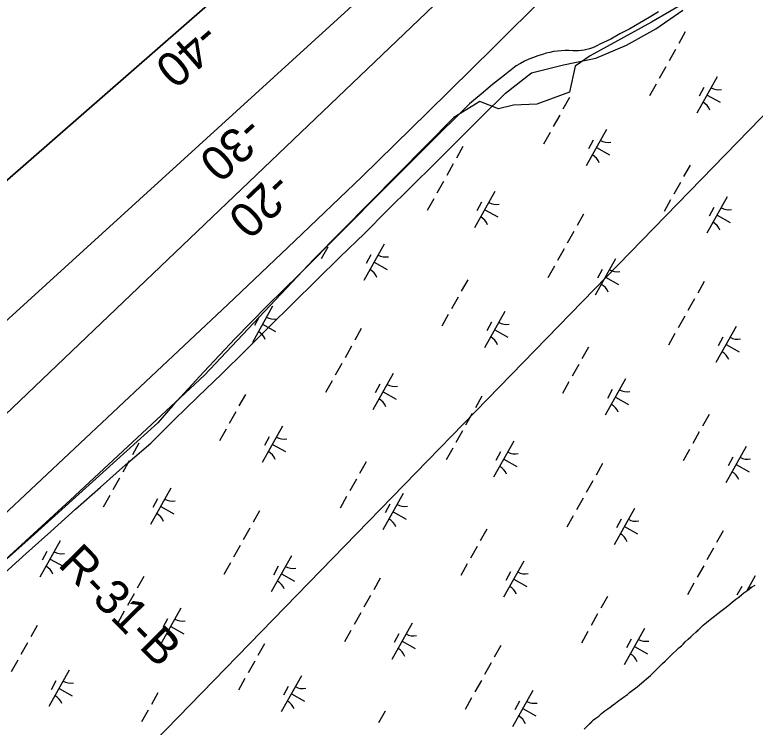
# Model space of a CAD drawing. Extents: x 3923531 to 3943530, y 207391 to 229799.
# Drawn here: x 3930996 to 3931887, y 212001 to 212858 of the extents above; entities that cross this region are included whole.
import ezdxf

# ---------------------------------------------------------------- set-up
doc = ezdxf.new("R2010")
doc.units = 0
for name, color, linetype in [('V-RIVR-EDGE', 7, 'Continuous'), ('V-RIVR-RANG-IDEN', 7, 'Continuous'), ('V-RRAP-FSHR', 7, 'Continuous'), ('V-TOPO-DPTH', 7, 'Continuous'), ('V-TOPO-MINR', 7, 'Continuous'), ('V-TOPO-MINR-IDEN', 7, 'Continuous'), ('V-TOPO-SHOR', 7, 'Continuous'), ('V-UTIL-LINE', 7, 'Continuous'), ('V-WETL-SWMP', 7, 'Continuous')]:
    doc.layers.add(name, color=color, linetype=linetype)

msp = doc.modelspace()

# ---------------------------------------------------------------- linework, layer by layer
at = {"layer": 'V-RIVR-EDGE'}
msp.add_lwpolyline([(3931806.48, 212875.19), (3931762.67, 212849.35), (3931688.52, 212808.91), (3931670.55, 212796.55), (3931663.81, 212765.1), (3931624.49, 212750.49), (3931596.4, 212749.37), (3931578.43, 212744.87), (3931555.96, 212753.86), (3931524.5, 212734.76), (3931355.99, 212564.01), (3931224.55, 212424.7), (3931062.78, 212274.17), (3930877.42, 212104.53)], dxfattribs=at)
at = {"layer": 'V-RRAP-FSHR'}
msp.add_lwpolyline([(3930979.93, 212183.18), (3931009.66, 212209.93), (3931039.5, 212236.57), (3931069.34, 212263.2), (3931099.35, 212289.65), (3931129.39, 212316.58), (3931159.75, 212342.87), (3931187.83, 212370.67), (3931216.59, 212398.47), (3931245.34, 212426.28), (3931273.78, 212454.4), (3931302.22, 212482.54), (3931330.65, 212510.67), (3931359.13, 212538.76), (3931387.61, 212566.84), (3931416.93, 212594.93), (3931444.57, 212623.19), (3931473.37, 212651.12), (3931501.51, 212679.21), (3931529.92, 212707.37), (3931558.2, 212735.65), (3931586.69, 212763.72), (3931618.12, 212788.32), (3931656.45, 212798.12), (3931695.57, 212806.14), (3931732.38, 212821.6), (3931767.67, 212841.5), (3931800.17, 212863.94)], dxfattribs=at)
at = {"layer": 'V-TOPO-DPTH'}
for points in [[(3930696.56, 212226.99), (3931622.64, 213069.98), (3931625.87, 213070.96), (3931629.26, 213071.55), (3931632.61, 213072.19), (3931635.76, 213073.25), (3931638.63, 213074.94), (3931641.3, 213077.06), (3931849.31, 213281.77), (3931932.2, 213361.55), (3932016.22, 213440.09), (3932101.96, 213516.75), (3932188.84, 213592.17), (3932358.19, 213735.93), (3932361.4, 213738.15), (3932364.79, 213739.91), (3932368.46, 213740.98), (3932372.32, 213741.58), (3932376.12, 213742.25), (3932379.68, 213743.44), (3932382.88, 213745.39), (3932385.85, 213747.87), (3932595.3, 213968.31)], [(3932595.3, 213968.31), (3932385.85, 213747.87), (3932382.88, 213745.39), (3932379.68, 213743.44), (3932376.12, 213742.25), (3932372.32, 213741.58), (3932368.46, 213740.98), (3932364.79, 213739.91), (3932361.4, 213738.15), (3932358.19, 213735.93), (3932188.84, 213592.17), (3932101.96, 213516.75), (3932016.22, 213440.09), (3931932.2, 213361.55), (3931849.31, 213281.77), (3931641.3, 213077.06), (3931638.63, 213074.94), (3931635.76, 213073.25), (3931632.61, 213072.19), (3931629.26, 213071.55), (3931625.87, 213070.96), (3931622.64, 213069.98), (3930696.56, 212226.99)], [(3930768.14, 212468.73), (3931535.57, 213138.53), (3931538.74, 213139.85), (3931542.06, 213140.71), (3931545.49, 213141.27), (3931548.86, 213141.9), (3931552.06, 213142.93), (3931554.99, 213144.56), (3931557.76, 213146.59), (3931734.7, 213304.83), (3931825.07, 213387.07), (3931914.46, 213470.33), (3932002.4, 213555.13), (3932089.36, 213640.96), (3932264.28, 213816.62)], [(3932264.28, 213816.62), (3932089.36, 213640.96), (3932002.4, 213555.13), (3931914.46, 213470.33), (3931825.07, 213387.07), (3931734.7, 213304.83), (3931557.76, 213146.59), (3931554.99, 213144.56), (3931552.06, 213142.93), (3931548.86, 213141.9), (3931545.49, 213141.27), (3931542.06, 213140.71), (3931538.74, 213139.85), (3931535.57, 213138.53), (3930768.14, 212468.73)], [(3932528.01, 213801.19), (3932507.12, 213780.69), (3932486.21, 213760.19), (3932465.3, 213739.7), (3932424.5, 213699.74), (3932422.94, 213698.24), (3932420.81, 213696.3), (3932420.27, 213695.83), (3931845.18, 213189.82), (3931816.27, 213164.23), (3931787.46, 213138.51), (3931758.82, 213112.62), (3931730.28, 213086.62), (3931674.64, 213035.61), (3931674, 213035.02), (3931673.36, 213034.42), (3931670.81, 213032.03), (3931669.54, 213030.84), (3930352.57, 211774.01)]]:
    msp.add_lwpolyline(points, dxfattribs=at)
at = {"layer": 'V-TOPO-MINR'}
for points in [[(3930836.96, 212119.61), (3931252.52, 212509.78), (3931333.35, 212586.34), (3931413.71, 212663.37), (3931493.4, 212741.11), (3931572.62, 212819.32), (3931696.28, 212942.47), (3931713.45, 212959.34), (3931730.77, 212976.05), (3931748.32, 212992.51), (3931766.02, 213008.82), (3931928.42, 213156.39), (3932018.55, 213239.05), (3932108.16, 213322.26), (3932197.01, 213406.28), (3932285.34, 213490.86), (3932438.94, 213639.3), (3932450.07, 213650.08), (3932461.17, 213660.88), (3932472.24, 213671.72), (3932483.29, 213682.58), (3932968.48, 214160.92)], [(3930696.56, 212226.99), (3931622.64, 213069.98), (3931625.87, 213070.96), (3931629.26, 213071.55), (3931632.61, 213072.19), (3931635.76, 213073.25), (3931638.63, 213074.94), (3931641.3, 213077.06), (3931849.31, 213281.77), (3931932.2, 213361.55), (3932016.22, 213440.09), (3932101.96, 213516.75), (3932188.84, 213592.17), (3932358.19, 213735.93), (3932361.4, 213738.15), (3932364.79, 213739.91), (3932368.46, 213740.98), (3932372.32, 213741.58), (3932376.12, 213742.25), (3932379.68, 213743.44), (3932382.88, 213745.39), (3932385.85, 213747.87), (3932595.3, 213968.31)], [(3930768.14, 212468.73), (3931535.57, 213138.53), (3931538.74, 213139.85), (3931542.06, 213140.71), (3931545.49, 213141.27), (3931548.86, 213141.9), (3931552.06, 213142.93), (3931554.99, 213144.56), (3931557.76, 213146.59), (3931734.7, 213304.83), (3931825.07, 213387.07), (3931914.46, 213470.33), (3932002.4, 213555.13), (3932089.36, 213640.96), (3932264.28, 213816.62)], [(3930352.57, 211774.01), (3931669.54, 213030.84), (3931670.81, 213032.03), (3931673.36, 213034.42), (3931674, 213035.02), (3931674.64, 213035.61), (3931730.28, 213086.62), (3931758.82, 213112.62), (3931787.46, 213138.51), (3931816.27, 213164.23), (3931845.18, 213189.82), (3932420.27, 213695.83), (3932420.81, 213696.3), (3932422.94, 213698.24), (3932424.5, 213699.74), (3932465.3, 213739.7), (3932486.21, 213760.19), (3932507.12, 213780.69), (3932528.01, 213801.19)]]:
    msp.add_lwpolyline(points, dxfattribs=at)
at = {"layer": 'V-TOPO-SHOR'}
msp.add_lwpolyline([(3931681.5, 211998.55), (3931685.29, 212002.46), (3931689.29, 212006.37), (3931692.88, 212009.89), (3931695.67, 212011.83), (3931699.06, 212014.36), (3931702.45, 212017.49), (3931706.44, 212020.61), (3931709.83, 212022.94), (3931712.61, 212024.89), (3931716.4, 212027.81), (3931719.19, 212029.96), (3931723.37, 212032.87), (3931725.77, 212034.82), (3931729.95, 212037.94), (3931733.54, 212040.47), (3931736.13, 212042.61), (3931739.32, 212045.15), (3931742.11, 212047.09), (3931745.1, 212049.63), (3931747.89, 212051.77), (3931750.29, 212053.72), (3931753.48, 212056.65), (3931756.47, 212059.19), (3931758.86, 212061.14), (3931761.26, 212063.09), (3931764.46, 212066.41), (3931768.45, 212070.52), (3931771.65, 212073.45), (3931775.65, 212077.55), (3931778.84, 212080.48), (3931782.64, 212084.2), (3931785.03, 212086.34), (3931788.03, 212089.47), (3931791.82, 212092.79), (3931795.42, 212096.31), (3931798.41, 212098.85), (3931800.61, 212101), (3931803.21, 212103.73), (3931806.6, 212106.86), (3931809.79, 212109.79), (3931812.19, 212111.93), (3931815.98, 212115.25), (3931818.58, 212117.79), (3931822.17, 212121.31), (3931824.77, 212123.65), (3931828.56, 212126.97), (3931830.95, 212128.92), (3931835.14, 212132.04), (3931838.13, 212134.58), (3931842.31, 212137.69), (3931845.9, 212140.42), (3931850.88, 212144.12), (3931854.47, 212147.04), (3931859.46, 212151.34), (3931864.04, 212155.04), (3931867.43, 212157.37), (3931870.82, 212160.1), (3931873.81, 212162.44), (3931877.4, 212165.17), (3931879.99, 212166.92), (3931882.98, 212169.26), (3931887.35, 212171.78)], dxfattribs=at)
at = {"layer": 'V-UTIL-LINE'}
msp.add_lwpolyline([(3939084.62, 223621.72), (3938057.71, 221140.48), (3938136.4, 220832.47), (3937591.63, 219695.21), (3936312.73, 217957.68), (3935106.6, 216231.89), (3934055.84, 214955.86), (3930691.13, 211497.88), (3930457.99, 211185.48)], dxfattribs=at)
at = {"layer": 'V-WETL-SWMP'}
for p, q in [((3931771.08, 212861.69), (3931759.57, 212854.78)), ((3931759.57, 212854.78), (3931747.95, 212848.04)), ((3931747.95, 212848.04), (3931736.23, 212841.48)), ((3931724.42, 212835.11), (3931713.38, 212828.77)), ((3931736.23, 212841.48), (3931724.42, 212835.11)), ((3931803.07, 212837.56), (3931795.27, 212823.59)), ((3931713.38, 212828.77), (3931700.49, 212822.91)), ((3931658.54, 212815.15), (3931653.88, 212814.95)), ((3931663.19, 212815.1), (3931658.54, 212815.15)), ((3931667.83, 212814.83), (3931663.19, 212815.1)), ((3931678.06, 212815.17), (3931674.66, 212814.85)), ((3931681.43, 212815.69), (3931678.06, 212815.17)), ((3931684.77, 212816.41), (3931681.43, 212815.69)), ((3931688.06, 212817.33), (3931684.77, 212816.41)), ((3931691.29, 212818.44), (3931688.06, 212817.33)), ((3931694.44, 212819.74), (3931691.29, 212818.44)), ((3931697.52, 212821.24), (3931694.44, 212819.74)), ((3931700.49, 212822.91), (3931697.52, 212821.24)), ((3931791.37, 212816.61), (3931783.57, 212802.64)), ((3931620.27, 212806.84), (3931614.98, 212804.65)), ((3931625.64, 212808.8), (3931620.27, 212806.84)), ((3931631.1, 212810.52), (3931625.64, 212808.8)), ((3931635.56, 212811.87), (3931631.1, 212810.52)), ((3931640.07, 212812.98), (3931635.56, 212811.87)), ((3931644.64, 212813.87), (3931640.07, 212812.98)), ((3931649.25, 212814.53), (3931644.64, 212813.87)), ((3931653.88, 212814.95), (3931649.25, 212814.53)), ((3931671.25, 212814.74), (3931667.83, 212814.83)), ((3931674.66, 212814.85), (3931671.25, 212814.74)), ((3931604.71, 212799.6), (3931599.75, 212796.74)), ((3931609.79, 212802.23), (3931604.71, 212799.6)), ((3931614.98, 212804.65), (3931609.79, 212802.23)), ((3931599.75, 212796.74), (3931585.41, 212785.63)), ((3931779.66, 212795.66), (3931771.86, 212781.69)), ((3931585.41, 212785.63), (3931571.25, 212774.27)), ((3931841.62, 212783.47), (3931817.24, 212739.82)), ((3931571.25, 212774.27), (3931557.29, 212762.68)), ((3931767.96, 212774.71), (3931760.16, 212760.74)), ((3931825.62, 212770.65), (3931819.77, 212760.17)), ((3931557.29, 212762.68), (3931543.52, 212750.86)), ((3931829.43, 212761.65), (3931845.15, 212752.87)), ((3931663.75, 212758.52), (3931655.94, 212744.56)), ((3931543.52, 212750.86), (3931492.2, 212700.02)), ((3931652.04, 212737.57), (3931644.24, 212723.6)), ((3931708.42, 212720.16), (3931684.04, 212676.51)), ((3931640.34, 212716.62), (3931632.53, 212702.65)), ((3931492.2, 212700.02), (3931441.03, 212649.01)), ((3931535.47, 212699.6), (3931527.66, 212685.63)), ((3931692.42, 212707.33), (3931686.57, 212696.86)), ((3931696.23, 212698.33), (3931711.94, 212689.55)), ((3931523.76, 212678.65), (3931515.96, 212664.68)), ((3931808.96, 212677.4), (3931801.16, 212663.43)), ((3931512.06, 212657.7), (3931504.25, 212643.73)), ((3931797.25, 212656.45), (3931789.45, 212642.48)), ((3931441.03, 212649.01), (3931390.03, 212597.85)), ((3931574.02, 212645.51), (3931549.63, 212601.86)), ((3931853.64, 212639.03), (3931829.25, 212595.38)), ((3931500.35, 212636.75), (3931492.55, 212622.78)), ((3931558.02, 212632.69), (3931552.16, 212622.21)), ((3931785.55, 212635.5), (3931777.75, 212621.53)), ((3931561.83, 212623.69), (3931577.54, 212614.91)), ((3931837.63, 212626.21), (3931831.78, 212615.73)), ((3931680.68, 212618.48), (3931672.88, 212604.51)), ((3931841.44, 212617.21), (3931857.16, 212608.43)), ((3931390.03, 212597.85), (3931339.19, 212546.51)), ((3931668.98, 212597.53), (3931661.17, 212583.56)), ((3931372.73, 212578.66), (3931364.93, 212564.69)), ((3931440.82, 212582.2), (3931416.43, 212538.55)), ((3931657.27, 212576.57), (3931649.47, 212562.61)), ((3931424.82, 212569.37), (3931418.96, 212558.9)), ((3931428.62, 212560.37), (3931444.34, 212551.59)), ((3931719.23, 212564.39), (3931694.85, 212520.74)), ((3931645.57, 212555.62), (3931637.76, 212541.65)), ((3931703.23, 212551.56), (3931697.38, 212541.09)), ((3931339.19, 212546.51), (3931319.52, 212527.25)), ((3931541.35, 212539.44), (3931533.55, 212525.47)), ((3931707.04, 212542.56), (3931722.75, 212533.78)), ((3931825.9, 212537.35), (3931818.09, 212523.39)), ((3931319.52, 212527.25), (3931300.01, 212507.82)), ((3931529.65, 212518.49), (3931521.84, 212504.52)), ((3931814.19, 212516.4), (3931806.39, 212502.43)), ((3931300.01, 212507.82), (3931280.66, 212488.22)), ((3931306.41, 212507.55), (3931282.03, 212463.9)), ((3931290.41, 212494.73), (3931284.56, 212484.25)), ((3931517.94, 212497.53), (3931510.14, 212483.57)), ((3931586.03, 212501.07), (3931561.65, 212457.42)), ((3931802.49, 212495.45), (3931794.68, 212481.48)), ((3931280.66, 212488.22), (3931261.48, 212468.47)), ((3931294.22, 212485.73), (3931309.93, 212476.95)), ((3931570.03, 212488.25), (3931564.18, 212477.77)), ((3931413.08, 212480.52), (3931405.27, 212466.55)), ((3931573.84, 212479.25), (3931589.55, 212470.47)), ((3931864.45, 212483.26), (3931840.06, 212439.61)), ((3931261.48, 212468.47), (3931242.46, 212448.55)), ((3931790.78, 212474.5), (3931782.98, 212460.53)), ((3931848.44, 212470.44), (3931842.59, 212459.96)), ((3931401.37, 212459.57), (3931393.57, 212445.6)), ((3931852.25, 212461.44), (3931867.97, 212452.66)), ((3931686.57, 212458.31), (3931678.76, 212444.35)), ((3931242.46, 212448.55), (3931223.62, 212428.47)), ((3931389.67, 212438.61), (3931381.86, 212424.65)), ((3931674.86, 212437.36), (3931667.06, 212423.39)), ((3931223.62, 212428.47), (3931204.94, 212408.24)), ((3931451.63, 212426.43), (3931427.24, 212382.78)), ((3931377.96, 212417.66), (3931370.16, 212403.69)), ((3931663.16, 212416.41), (3931655.35, 212402.44)), ((3931731.24, 212419.95), (3931706.86, 212376.3)), ((3931204.94, 212408.24), (3931186.43, 212387.85)), ((3931435.62, 212413.6), (3931429.77, 212403.13)), ((3931715.24, 212407.12), (3931709.39, 212396.65)), ((3931273.75, 212401.48), (3931265.94, 212387.51)), ((3931439.43, 212404.6), (3931455.15, 212395.82)), ((3931558.29, 212399.39), (3931550.49, 212385.43)), ((3931719.05, 212398.12), (3931734.77, 212389.34)), ((3931186.43, 212387.85), (3931168.1, 212367.3)), ((3931262.04, 212380.53), (3931254.24, 212366.56)), ((3931546.58, 212378.44), (3931538.78, 212364.47)), ((3931831.78, 212377.19), (3931823.98, 212363.22)), ((3931168.1, 212367.3), (3931118.66, 212322.39)), ((3931318.42, 212363.11), (3931294.04, 212319.46)), ((3931250.34, 212359.57), (3931242.53, 212345.61)), ((3931534.88, 212357.49), (3931527.08, 212343.52)), ((3931820.07, 212356.24), (3931812.27, 212342.27)), ((3931302.42, 212350.29), (3931296.57, 212339.81)), ((3931596.84, 212345.3), (3931572.45, 212301.65)), ((3931145.47, 212342.56), (3931137.67, 212328.59)), ((3931306.23, 212341.29), (3931321.95, 212332.51)), ((3931523.17, 212336.54), (3931515.37, 212322.57)), ((3931808.37, 212335.29), (3931800.57, 212321.32)), ((3931876.46, 212338.82), (3931852.07, 212295.17)), ((3931580.84, 212332.48), (3931574.98, 212322)), ((3931860.46, 212326), (3931854.6, 212315.52)), ((3931118.66, 212322.39), (3931069.09, 212277.62)), ((3931133.76, 212321.61), (3931125.96, 212307.64)), ((3931418.96, 212320.35), (3931411.16, 212306.39)), ((3931584.65, 212323.48), (3931600.36, 212314.7)), ((3931703.5, 212318.27), (3931695.7, 212304.3)), ((3931864.27, 212317), (3931879.98, 212308.22)), ((3931122.06, 212300.65), (3931114.26, 212286.69)), ((3931407.26, 212299.4), (3931399.45, 212285.43)), ((3931691.8, 212297.32), (3931683.99, 212283.35)), ((3931184.02, 212288.47), (3931159.63, 212244.82)), ((3931463.64, 212281.99), (3931439.25, 212238.34)), ((3931069.09, 212277.62), (3931019.39, 212232.99)), ((3931110.35, 212279.7), (3931102.55, 212265.73)), ((3931168.02, 212275.64), (3931162.16, 212265.17)), ((3931395.55, 212278.45), (3931387.75, 212264.48)), ((3931680.09, 212276.37), (3931672.29, 212262.4)), ((3931171.83, 212266.64), (3931187.54, 212257.86)), ((3931447.64, 212269.16), (3931441.78, 212258.69)), ((3931742.05, 212264.18), (3931717.67, 212220.53)), ((3931290.68, 212261.43), (3931282.88, 212247.47)), ((3931451.45, 212260.16), (3931467.16, 212251.38)), ((3931668.39, 212255.41), (3931660.58, 212241.45)), ((3931726.05, 212251.35), (3931720.2, 212240.88)), ((3931278.98, 212240.48), (3931271.17, 212226.51)), ((3931564.17, 212239.23), (3931556.37, 212225.26)), ((3931729.86, 212242.35), (3931745.57, 212233.57)), ((3931848.72, 212237.15), (3931840.91, 212223.18)), ((3931019.39, 212232.99), (3930969.56, 212188.52)), ((3931050.82, 212225.15), (3931026.43, 212181.5)), ((3931267.27, 212219.53), (3931259.47, 212205.56)), ((3931552.47, 212218.28), (3931544.67, 212204.31)), ((3931034.82, 212212.33), (3931028.96, 212201.85)), ((3931837.01, 212216.19), (3931829.21, 212202.23)), ((3931038.63, 212203.33), (3931054.34, 212194.55)), ((3931329.23, 212207.34), (3931304.85, 212163.69)), ((3931608.85, 212200.86), (3931584.47, 212157.21)), ((3931255.57, 212198.58), (3931247.76, 212184.61)), ((3931313.23, 212194.52), (3931307.38, 212184.04)), ((3931540.76, 212197.33), (3931532.96, 212183.36)), ((3931825.31, 212195.24), (3931817.5, 212181.27)), ((3931151.35, 212182.39), (3931143.55, 212168.43)), ((3931317.04, 212185.52), (3931332.75, 212176.74)), ((3931592.85, 212188.04), (3931587, 212177.56)), ((3931887.27, 212183.05), (3931877.18, 212165.01)), ((3931435.9, 212180.31), (3931428.09, 212166.34)), ((3931596.66, 212179.04), (3931612.37, 212170.26)), ((3931813.6, 212174.29), (3931805.8, 212160.32)), ((3931871.26, 212170.23), (3931865.41, 212159.75)), ((3931873.81, 212162.44), (3931877.4, 212165.17)), ((3931877.4, 212165.17), (3931879.99, 212166.92)), ((3931879.99, 212166.92), (3931882.98, 212169.26)), ((3931882.98, 212169.26), (3931887.35, 212171.78)), ((3931139.65, 212161.44), (3931131.85, 212147.47)), ((3931424.19, 212159.36), (3931416.39, 212145.39)), ((3931709.39, 212158.11), (3931701.58, 212144.14)), ((3931864.05, 212155.04), (3931867.43, 212157.37)), ((3931867.43, 212157.37), (3931870.82, 212160.1)), ((3931870.82, 212160.1), (3931873.81, 212162.44)), ((3931850.88, 212144.12), (3931854.47, 212147.04)), ((3931854.47, 212147.04), (3931859.46, 212151.34)), ((3931859.46, 212151.34), (3931864.05, 212155.04)), ((3931127.94, 212140.49), (3931120.14, 212126.52)), ((3931196.03, 212144.03), (3931171.65, 212100.38)), ((3931412.49, 212138.41), (3931404.68, 212124.44)), ((3931842.31, 212137.69), (3931845.9, 212140.42)), ((3931845.9, 212140.42), (3931850.88, 212144.12)), ((3931180.03, 212131.2), (3931174.18, 212120.73)), ((3931697.68, 212137.15), (3931689.88, 212123.19)), ((3931828.56, 212126.97), (3931830.95, 212128.92)), ((3931830.95, 212128.92), (3931835.14, 212132.04)), ((3931835.14, 212132.04), (3931838.13, 212134.57)), ((3931838.13, 212134.57), (3931842.31, 212137.69)), ((3931023.08, 212123.47), (3931015.27, 212109.51)), ((3931183.84, 212122.2), (3931199.55, 212113.42)), ((3931474.45, 212126.22), (3931450.06, 212082.57)), ((3931815.98, 212115.25), (3931822.17, 212121.31)), ((3931822.17, 212121.31), (3931824.77, 212123.65)), ((3931824.77, 212123.65), (3931828.56, 212126.97)), ((3931400.78, 212117.45), (3931392.98, 212103.49)), ((3931458.44, 212113.39), (3931452.59, 212102.92)), ((3931685.98, 212116.2), (3931678.17, 212102.23)), ((3931754.07, 212119.74), (3931729.68, 212076.09)), ((3931809.79, 212109.79), (3931812.19, 212111.93)), ((3931812.19, 212111.93), (3931815.98, 212115.25)), ((3931011.37, 212102.52), (3931003.57, 212088.55)), ((3931462.25, 212104.39), (3931477.97, 212095.61)), ((3931738.06, 212106.92), (3931732.21, 212096.44)), ((3931800.61, 212100.99), (3931803.21, 212103.73)), ((3931803.21, 212103.73), (3931806.6, 212106.86)), ((3931806.6, 212106.86), (3931809.79, 212109.79)), ((3931296.57, 212101.27), (3931288.76, 212087.3)), ((3931581.11, 212099.19), (3931573.31, 212085.22)), ((3931741.87, 212097.91), (3931757.59, 212089.14)), ((3931791.82, 212092.79), (3931795.42, 212096.31)), ((3931795.42, 212096.31), (3931798.41, 212098.85)), ((3931798.41, 212098.85), (3931800.61, 212100.99)), ((3931782.64, 212084.2), (3931785.03, 212086.35)), ((3931785.03, 212086.35), (3931788.03, 212089.47)), ((3931788.03, 212089.47), (3931791.82, 212092.79)), ((3930999.67, 212081.57), (3930991.86, 212067.6)), ((3931284.86, 212080.32), (3931277.06, 212066.35)), ((3931569.41, 212078.23), (3931561.6, 212064.27)), ((3931771.65, 212073.45), (3931775.65, 212077.55)), ((3931775.65, 212077.55), (3931778.84, 212080.48)), ((3931778.84, 212080.48), (3931782.64, 212084.2)), ((3931061.63, 212069.38), (3931037.24, 212025.73)), ((3931764.46, 212066.41), (3931768.45, 212070.52)), ((3931768.45, 212070.52), (3931771.65, 212073.45)), ((3931273.16, 212059.37), (3931265.35, 212045.4)), ((3931341.25, 212062.9), (3931316.86, 212019.25)), ((3931753.48, 212056.65), (3931756.47, 212059.19)), ((3931756.47, 212059.19), (3931761.26, 212063.09)), ((3931761.26, 212063.09), (3931764.46, 212066.41)), ((3931045.62, 212056.56), (3931039.77, 212046.08)), ((3931325.24, 212050.08), (3931319.39, 212039.6)), ((3931557.7, 212057.28), (3931549.9, 212043.31)), ((3931742.11, 212047.09), (3931745.1, 212049.63)), ((3931745.1, 212049.63), (3931747.89, 212051.77)), ((3931747.89, 212051.77), (3931750.28, 212053.72)), ((3931750.28, 212053.72), (3931753.48, 212056.65)), ((3931049.43, 212047.56), (3931065.15, 212038.78)), ((3931168.29, 212042.35), (3931160.49, 212028.38)), ((3931329.05, 212041.08), (3931344.77, 212032.3)), ((3931619.66, 212045.09), (3931595.27, 212001.44)), ((3931729.95, 212037.94), (3931733.54, 212040.47)), ((3931733.54, 212040.47), (3931736.13, 212042.61)), ((3931736.13, 212042.61), (3931739.32, 212045.15)), ((3931739.32, 212045.15), (3931742.11, 212047.09)), ((3931546, 212036.33), (3931538.19, 212022.36)), ((3931603.66, 212032.27), (3931597.81, 212021.79)), ((3931719.19, 212029.96), (3931723.37, 212032.87)), ((3931723.37, 212032.87), (3931725.77, 212034.82)), ((3931725.77, 212034.82), (3931729.95, 212037.94)), ((3931607.47, 212023.27), (3931623.18, 212014.49)), ((3931706.44, 212020.61), (3931709.83, 212022.94)), ((3931709.83, 212022.94), (3931712.62, 212024.89)), ((3931712.62, 212024.89), (3931716.4, 212027.81)), ((3931716.4, 212027.81), (3931719.19, 212029.96)), ((3931156.59, 212021.4), (3931148.78, 212007.43)), ((3931441.78, 212020.15), (3931433.98, 212006.18)), ((3931695.67, 212011.83), (3931699.06, 212014.37)), ((3931699.06, 212014.37), (3931702.45, 212017.49)), ((3931702.45, 212017.49), (3931706.44, 212020.61)), ((3931685.29, 212002.46), (3931692.88, 212009.89)), ((3931692.88, 212009.89), (3931695.67, 212011.83)), ((3931681.5, 211998.55), (3931685.29, 212002.46))]:
    msp.add_line(p, q, dxfattribs=at)
for centre, start, end in [((3931843.11, 212785.64), 240.03808, 281.58174), ((3931816.17, 212737.42), 20.03808, 61.58174), ((3931709.91, 212722.33), 240.03808, 281.58174), ((3931682.97, 212674.1), 20.03808, 61.58174), ((3931575.5, 212647.68), 240.03808, 281.58174), ((3931855.12, 212641.21), 240.03808, 281.58174), ((3931548.56, 212599.46), 20.03808, 61.58174), ((3931828.18, 212592.98), 20.03808, 61.58174), ((3931442.3, 212584.37), 240.03808, 281.58174), ((3931415.36, 212536.14), 20.03808, 61.58174), ((3931720.72, 212566.56), 240.03808, 281.58174), ((3931693.77, 212518.33), 20.03808, 61.58174), ((3931307.9, 212509.72), 240.03808, 281.58174), ((3931587.52, 212503.25), 240.03808, 281.58174), ((3931280.95, 212461.5), 20.03808, 61.58174), ((3931560.57, 212455.02), 20.03808, 61.58174), ((3931865.93, 212485.43), 240.03808, 281.58174), ((3931838.99, 212437.21), 20.03808, 61.58174), ((3931453.11, 212428.6), 240.03808, 281.58174), ((3931732.73, 212422.12), 240.03808, 281.58174), ((3931426.17, 212380.37), 20.03808, 61.58174), ((3931705.79, 212373.89), 20.03808, 61.58174), ((3931319.91, 212365.29), 240.03808, 281.58174), ((3931292.97, 212317.06), 20.03808, 61.58174), ((3931598.32, 212347.47), 240.03808, 281.58174), ((3931877.94, 212341), 240.03808, 281.58174), ((3931571.38, 212299.25), 20.03808, 61.58174), ((3931851, 212292.77), 20.03808, 61.58174), ((3931185.5, 212290.64), 240.03808, 281.58174), ((3931465.12, 212284.16), 240.03808, 281.58174), ((3931158.56, 212242.41), 20.03808, 61.58174), ((3931438.18, 212235.93), 20.03808, 61.58174), ((3931743.54, 212266.35), 240.03808, 281.58174), ((3931716.6, 212218.12), 20.03808, 61.58174), ((3931052.3, 212227.33), 240.03808, 281.58174), ((3931025.36, 212179.1), 20.03808, 61.58174), ((3931330.72, 212209.51), 240.03808, 281.58174), ((3931610.34, 212203.04), 240.03808, 281.58174), ((3931303.78, 212161.29), 20.03808, 61.58174), ((3931583.4, 212154.81), 20.03808, 61.58174), ((3931888.75, 212185.23), 240.03808, 248.81429), ((3931197.52, 212146.2), 240.03808, 281.58174), ((3931170.58, 212097.97), 20.03808, 61.58174), ((3931475.93, 212128.39), 240.03808, 281.58174), ((3931755.55, 212121.91), 240.03808, 281.58174), ((3931448.99, 212080.16), 20.03808, 61.58174), ((3931728.61, 212073.69), 20.03808, 61.58174), ((3931063.11, 212071.55), 240.03808, 281.58174), ((3931342.73, 212065.08), 240.03808, 281.58174), ((3931036.17, 212023.33), 20.03808, 61.58174), ((3931315.79, 212016.85), 20.03808, 61.58174), ((3931621.15, 212047.27), 240.03808, 281.58174), ((3931594.2, 211999.04), 20.03808, 61.58174)]:
    msp.add_arc(centre, 17.62, start, end, dxfattribs=at)

# ---------------------------------------------------------------- texts
at = {"layer": 'V-RIVR-RANG-IDEN'}
msp.add_text('R-31-B', height=41.5, rotation=314.71729, dxfattribs=at).set_placement((3931046.87, 212195.77))
at = {"layer": 'V-TOPO-MINR-IDEN'}
for s, rotation, p in [('-40', 221.1145, (3931222.42, 212851.45)), ('-30', 222.31101, (3931274.47, 212739.03)), ('-20', 223.66158, (3931308.07, 212671.53))]:
    msp.add_text(s, height=41.5, rotation=rotation, dxfattribs=at).set_placement(p)

doc.saveas('drawing.dxf')
